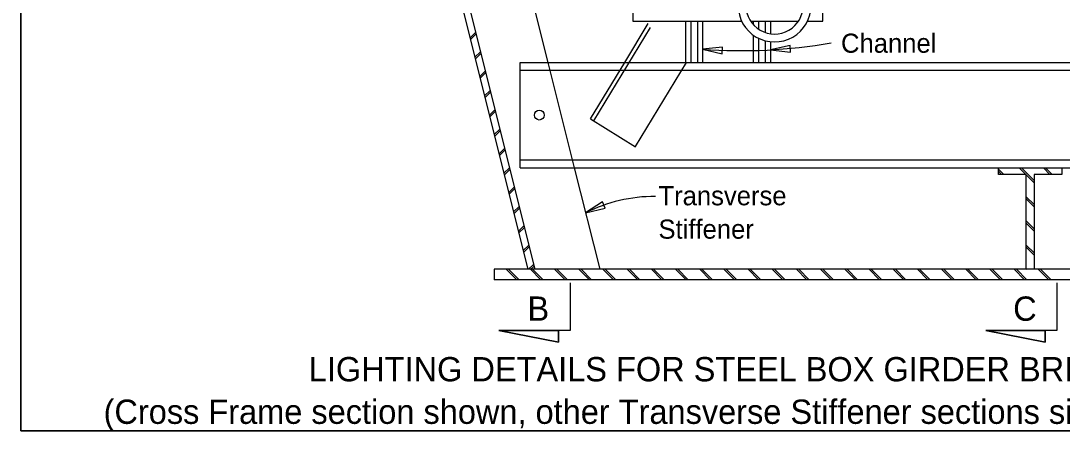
# Model space of a CAD drawing. Extents: x 0 to 30.8, y 0 to 21.2.
# Drawn here: x 0 to 8.22, y 0 to 3.24 of the extents above; entities that cross this region are included whole.
import ezdxf

# ---------------------------------------------------------------- set-up
doc = ezdxf.new("R2010")
doc.units = 0
for name, color, linetype in [('ActivePts-ConstElements', 7, 'Continuous'), ('Dimension', 7, 'Continuous'), ('Lighting', 7, 'Continuous'), ('Miscellaneous', 7, 'Continuous'), ('Miscellaneous1', 7, 'Continuous'), ('SteelGirder', 7, 'Continuous'), ('SteelGirder_h', 7, 'Continuous'), ('TextStructures', 7, 'Continuous')]:
    doc.layers.add(name, color=color, linetype=linetype)

msp = doc.modelspace()

# ---------------------------------------------------------------- linework, layer by layer
at = {"layer": 'ActivePts-ConstElements'}
msp.add_lwpolyline([(0, 0), (30.7879, 0), (30.7879, 19.4596), (0, 19.4596)], close=True, dxfattribs=at)
at = {"layer": 'Dimension'}
for p, q in [((4.3372, 1.1694), (4.3372, 0.7944)), ((8.1797, 1.1694), (8.1797, 0.7944)), ((4.3372, 0.7944), (3.7747, 0.7944)), ((3.7747, 0.7944), (4.2434, 0.7007)), ((4.2434, 0.7007), (4.2434, 0.7944)), ((8.1797, 0.7944), (7.6172, 0.7944)), ((7.6172, 0.7944), (8.0859, 0.7007)), ((8.0859, 0.7007), (8.0859, 0.7944))]:
    msp.add_line(p, q, dxfattribs=at)
for points in [[(5.918, 3.0115), (6.0754, 2.9938), (6.0725, 3.0466)], [(5.3822, 3.0171), (5.5359, 2.9788), (5.54, 3.0315)], [(4.4582, 1.7229), (4.6119, 1.7613), (4.5907, 1.8097)], [(4.2434, 0.7944), (4.2434, 0.7007), (3.7747, 0.7944)], [(8.0859, 0.7944), (8.0859, 0.7007), (7.6172, 0.7944)]]:
    msp.add_lwpolyline(points, close=True, dxfattribs=at)
msp.add_arc((5.6925, 7.0505), 4.0453, 265.60117, 280.01859, dxfattribs=at)
msp.add_ellipse((5.0007, 0.5401), major_axis=(-0.0084, -1.3128), ratio=0.953713, start_param=3.141601, end_param=3.59647, dxfattribs=at)
at = {"layer": 'Lighting'}
for p, q in [((5.2468, 3.2371), (5.2468, 2.9127)), ((5.2884, 3.2371), (5.2884, 2.9127)), ((5.3406, 3.2371), (5.3406, 2.9127)), ((5.3822, 3.2371), (5.3822, 2.9127)), ((5.7826, 3.2371), (5.7826, 3.2112)), ((5.8242, 3.2371), (5.8242, 3.175)), ((5.8764, 3.2371), (5.8764, 3.1489)), ((5.918, 3.2371), (5.918, 3.1388)), ((5.7826, 3.1278), (5.7826, 2.9127)), ((5.8242, 3.103), (5.8242, 2.9127)), ((5.8764, 3.0836), (5.8764, 2.9127)), ((5.918, 3.0757), (5.918, 2.9127))]:
    msp.add_line(p, q, dxfattribs=at)
for radius, start, end in [(0.2882, 179.99549, 0.00006), (0.2257, 180, 0.00003)]:
    msp.add_arc((5.9504, 3.3621), radius, start, end, dxfattribs=at)
at = {"layer": 'Miscellaneous'}
for p, q in [((3.5466, 3.106), (3.5895, 3.149)), ((3.5501, 3.0919), (3.5931, 3.1348)), ((3.5848, 2.9533), (3.6277, 2.9962)), ((3.5883, 2.9391), (3.6313, 2.9821)), ((3.6229, 2.8005), (3.6659, 2.8435)), ((3.6265, 2.7864), (3.6694, 2.8293)), ((3.6611, 2.6478), (3.7041, 2.6908)), ((3.6647, 2.6336), (3.7076, 2.6766)), ((3.6993, 2.4951), (3.7423, 2.538)), ((3.7028, 2.4809), (3.7458, 2.5239)), ((3.7375, 2.3423), (3.7805, 2.3853)), ((3.741, 2.3282), (3.784, 2.3711)), ((3.7757, 2.1896), (3.8186, 2.2325)), ((3.7792, 2.1754), (3.8222, 2.2184)), ((3.8139, 2.0369), (3.8568, 2.0798)), ((3.8174, 2.0227), (3.8604, 2.0657)), ((7.7605, 2.0272), (7.7181, 2.0696)), ((7.9337, 2.0272), (7.8816, 2.0794)), ((7.9994, 1.9793), (7.8993, 2.0794)), ((8.1246, 2.0272), (8.0725, 2.0794)), ((8.1423, 2.0272), (8.0902, 2.0794)), ((7.7428, 2.0272), (7.7181, 2.052)), ((7.9994, 1.9616), (7.9369, 2.024)), ((3.852, 1.8841), (3.895, 1.9271)), ((3.8556, 1.87), (3.8985, 1.9129)), ((7.9994, 1.7883), (7.9369, 1.8508)), ((7.9994, 1.7707), (7.9369, 1.8331)), ((3.8902, 1.7314), (3.9332, 1.7743)), ((3.8938, 1.7172), (3.9367, 1.7602)), ((7.9994, 1.5974), (7.9369, 1.6599)), ((3.9284, 1.5786), (3.9714, 1.6216)), ((3.932, 1.5645), (3.9749, 1.6075)), ((7.9994, 1.5797), (7.9369, 1.6422)), ((3.9666, 1.4259), (4.0096, 1.4689)), ((3.9701, 1.4118), (4.0131, 1.4547)), ((7.9994, 1.4065), (7.9369, 1.4689)), ((7.9994, 1.3888), (7.9369, 1.4513)), ((4.0089, 1.2773), (4.0477, 1.3161)), ((3.9153, 1.1941), (3.832, 1.2774)), ((3.9329, 1.1941), (3.8497, 1.2774)), ((4.1062, 1.1941), (4.0229, 1.2774)), ((4.0266, 1.2773), (4.0513, 1.302)), ((4.1239, 1.1941), (4.0406, 1.2774)), ((4.2971, 1.1941), (4.2138, 1.2774)), ((4.3148, 1.1941), (4.2315, 1.2774)), ((4.488, 1.1941), (4.4047, 1.2774)), ((4.5057, 1.1941), (4.4224, 1.2774)), ((4.6789, 1.1941), (4.5957, 1.2774)), ((4.6966, 1.1941), (4.6133, 1.2774)), ((4.8699, 1.1941), (4.7866, 1.2774)), ((4.8875, 1.1941), (4.8043, 1.2774)), ((5.0608, 1.1941), (4.9775, 1.2774)), ((5.0785, 1.1941), (4.9952, 1.2774)), ((5.2517, 1.1941), (5.1684, 1.2774)), ((5.2694, 1.1941), (5.1861, 1.2774)), ((5.4426, 1.1941), (5.3593, 1.2774)), ((5.4603, 1.1941), (5.377, 1.2774)), ((5.6335, 1.1941), (5.5503, 1.2774)), ((5.6512, 1.1941), (5.5679, 1.2774)), ((5.8245, 1.1941), (5.7412, 1.2774)), ((5.8421, 1.1941), (5.7588, 1.2774)), ((6.0154, 1.1941), (5.9321, 1.2774)), ((6.033, 1.1941), (5.9498, 1.2774)), ((6.2063, 1.1941), (6.123, 1.2774)), ((6.224, 1.1941), (6.1407, 1.2774)), ((6.3972, 1.1941), (6.3139, 1.2774)), ((6.4149, 1.1941), (6.3316, 1.2774)), ((6.5881, 1.1941), (6.5048, 1.2774)), ((6.6058, 1.1941), (6.5225, 1.2774)), ((6.779, 1.1941), (6.6958, 1.2774)), ((6.7967, 1.1941), (6.7134, 1.2774)), ((6.97, 1.1941), (6.8867, 1.2774)), ((6.9876, 1.1941), (6.9044, 1.2774)), ((7.1609, 1.1941), (7.0776, 1.2774)), ((7.1786, 1.1941), (7.0953, 1.2774)), ((7.3518, 1.1941), (7.2685, 1.2774)), ((7.3695, 1.1941), (7.2862, 1.2774)), ((7.5427, 1.1941), (7.4594, 1.2774)), ((7.5604, 1.1941), (7.4771, 1.2774)), ((7.7336, 1.1941), (7.6504, 1.2774)), ((7.7513, 1.1941), (7.668, 1.2774)), ((7.9246, 1.1941), (7.8413, 1.2774)), ((7.9422, 1.1941), (7.859, 1.2774)), ((7.9377, 1.2772), (7.9369, 1.278)), ((8.1155, 1.1941), (8.0322, 1.2774)), ((8.1332, 1.1941), (8.0499, 1.2774)), ((3.742, 1.1941), (3.7374, 1.1987))]:
    msp.add_line(p, q, dxfattribs=at)
at = {"layer": 'Miscellaneous1'}
msp.add_lwpolyline([(0, 19.8), (30.8, 19.8), (30.8, 0), (0, 0)], close=True, dxfattribs=at)
at = {"layer": 'SteelGirder'}
for p, q in [((2.4413, 7.5273), (4.0037, 1.2773)), ((2.495, 7.5273), (4.0574, 1.2773)), ((3.1739, 6.8606), (4.161, 2.9127)), ((4.7678, 2.9127), (4.9527, 3.2183)), ((3.9428, 2.0794), (3.9428, 2.9126)), ((3.9428, 2.9126), (8.7519, 2.9126)), ((3.9428, 2.8502), (8.7519, 2.8502)), ((3.9428, 2.1419), (8.7519, 2.1419)), ((3.9428, 2.0794), (8.7519, 2.0794)), ((4.3691, 2.0794), (4.5696, 1.2774)), ((4.4681, 1.2773), (3.7374, 1.2773)), ((3.7374, 1.2773), (3.7374, 1.1941)), ((3.7374, 1.2773), (3.7374, 1.1941)), ((7.9683, 1.2773), (4.4682, 1.2773)), ((8.7519, 1.2774), (7.9683, 1.2774)), ((8.7519, 1.1941), (3.7374, 1.1941))]:
    msp.add_line(p, q, dxfattribs=at)
for points in [[(6.2101, 3.2371), (6.3324, 3.2371), (6.3324, 6.4871), (5.4444, 6.4871)], [(4.8324, 5.3453), (4.8324, 3.2371), (5.6908, 3.2371)], [(5.7626, 3.2371), (6.1383, 3.2371)]]:
    msp.add_lwpolyline(points, dxfattribs=at)
msp.add_lwpolyline([(7.9369, 1.2772), (7.9369, 2.0272), (7.7181, 2.0272), (7.7181, 2.0794), (8.2181, 2.0794), (8.2181, 2.0272), (7.9994, 2.0272), (7.9994, 1.2773)], close=True, dxfattribs=at)
msp.add_circle((4.0931, 2.496), 0.0391, dxfattribs=at)
at = {"layer": 'SteelGirder_h'}
for p, q in [((4.5241, 2.4496), (4.9713, 3.1888)), ((4.1607, 2.9126), (4.3691, 2.0794)), ((4.4976, 2.4661), (4.7678, 2.9127)), ((4.8529, 2.2482), (5.2549, 2.9127)), ((4.4976, 2.4661), (4.8516, 2.246))]:
    msp.add_line(p, q, dxfattribs=at)

# ---------------------------------------------------------------- texts
at = {"layer": 'Dimension'}
for s, height, p in [('Transverse', 0.1512, (5.0338, 1.7832)), ('Stiffener', 0.1512, (5.0338, 1.5192)), ('LIGHTING DETAILS FOR STEEL BOX GIRDER BRIDGE', 0.192, (2.2732, 0.3922)), ('(Cross Frame section shown, other Transverse Stiffener sections similar)', 0.192, (0.6534, 0.0562))]:
    msp.add_text(s, height=height, dxfattribs=at).set_placement(p)
at = {"layer": 'TextStructures'}
for s, height, p in [('Channel', 0.1512, (6.4749, 2.9884)), ('B', 0.192, (3.9997, 0.8708)), ('C', 0.192, (7.8339, 0.8708))]:
    msp.add_text(s, height=height, dxfattribs=at).set_placement(p)

doc.saveas('drawing.dxf')
